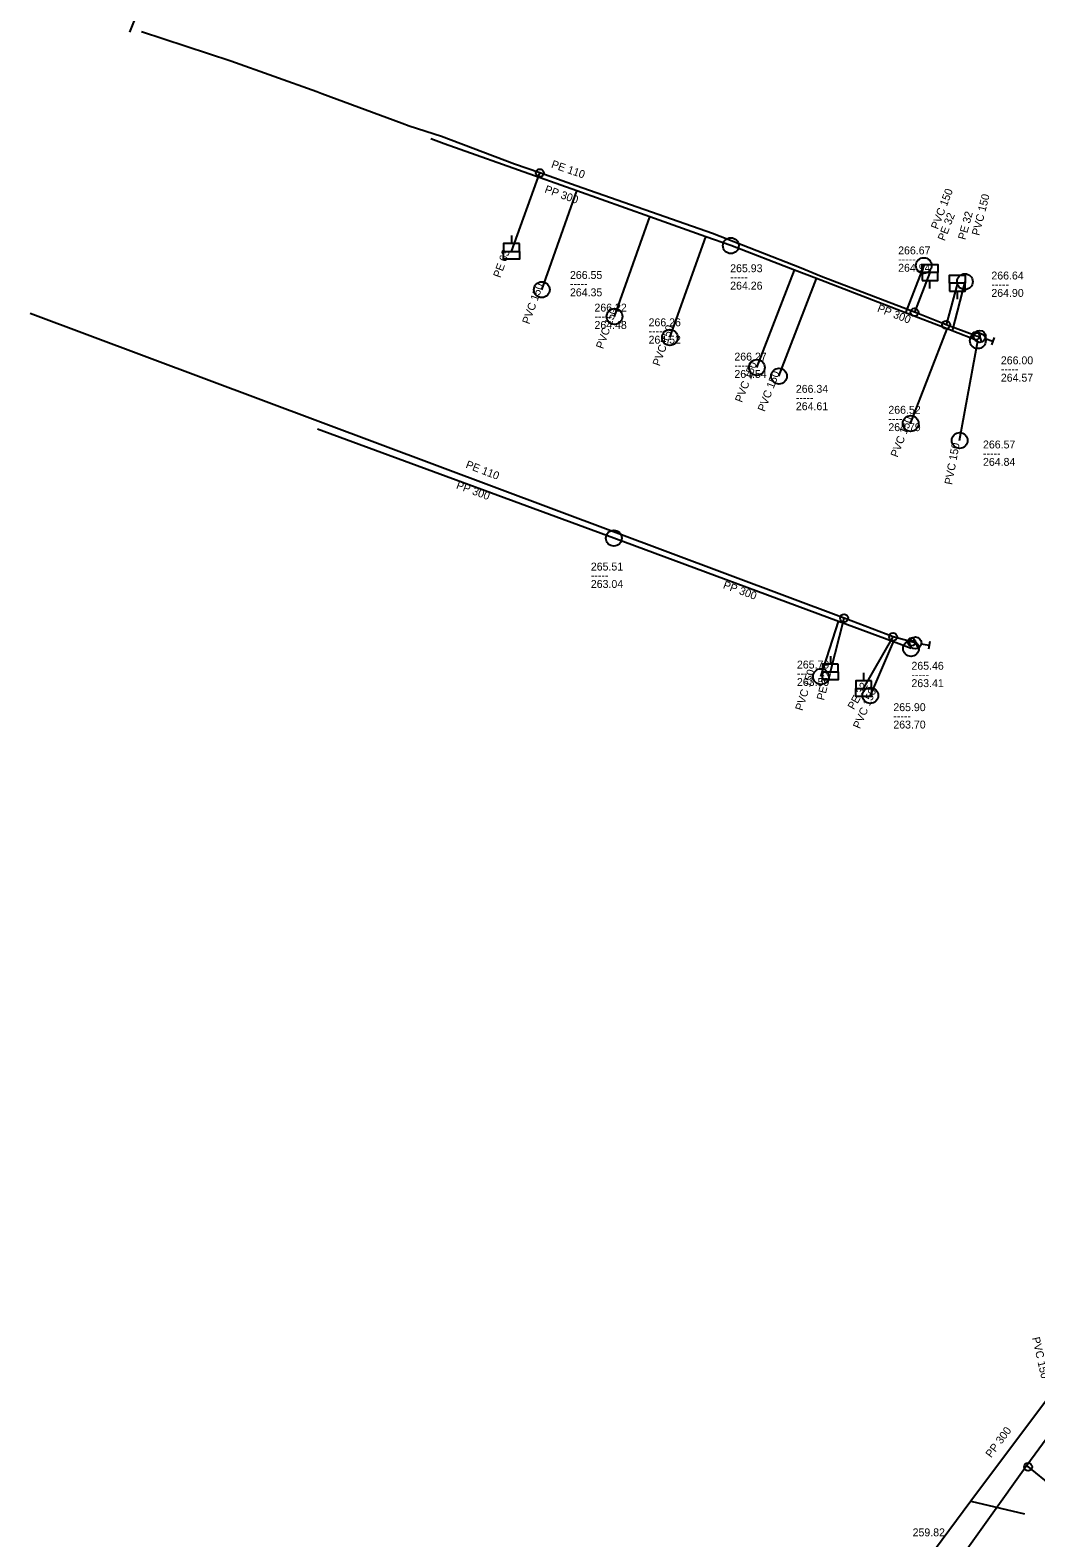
# Model space of a CAD drawing. Extents: x -770828 to -770111, y -1050344 to -1049447.
# Drawn here: x -770717.1 to -770589.8, y -1049916.1 to -1049725.3 of the extents above; entities that cross this region are included whole.
import ezdxf

# ---------------------------------------------------------------- set-up
doc = ezdxf.new("R2010")
doc.units = 0
doc.layers.add('Level 0', color=7, linetype='Continuous')

msp = doc.modelspace()

# ---------------------------------------------------------------- linework, layer by layer
at = {"layer": 'Level 0'}
for p, q in [((-770692.65, -1049695.96), (-770704.51, -1049725.54)), ((-770691.67, -1049729.23), (-770703, -1049725.52)), ((-770680.8, -1049733.09), (-770691.67, -1049729.23)), ((-770680.15, -1049733.34), (-770680.8, -1049733.09)), ((-770669.97, -1049737.13), (-770680.15, -1049733.34)), ((-770669.12, -1049737.44), (-770669.97, -1049737.13)), ((-770665.02, -1049738.76), (-770669.12, -1049737.44)), ((-770664.68, -1049739.67), (-770666.37, -1049739.07)), ((-770655.79, -1049742.26), (-770665.02, -1049738.76)), ((-770662.67, -1049740.39), (-770664.68, -1049739.67)), ((-770647.88, -1049745.64), (-770662.67, -1049740.39)), ((-770652.57, -1049743.37), (-770655.79, -1049742.26)), ((-770656.16, -1049753.29), (-770652.57, -1049743.37)), ((-770647.95, -1049744.98), (-770652.57, -1049743.37)), ((-770630.69, -1049751.04), (-770647.95, -1049744.98)), ((-770652.32, -1049758.14), (-770647.88, -1049745.64)), ((-770638.64, -1049748.93), (-770647.88, -1049745.64)), ((-770643.12, -1049761.54), (-770638.64, -1049748.93)), ((-770631.57, -1049751.44), (-770638.64, -1049748.93)), ((-770656.16, -1049751.29), (-770656.16, -1049752.29)), ((-770636.1, -1049764.19), (-770631.57, -1049751.44)), ((-770628.39, -1049752.57), (-770631.57, -1049751.44)), ((-770619.5, -1049755.42), (-770630.69, -1049751.04)), ((-770620.35, -1049755.67), (-770628.39, -1049752.57)), ((-770625.09, -1049767.99), (-770620.35, -1049755.67)), ((-770617.55, -1049756.74), (-770620.35, -1049755.67)), ((-770616.95, -1049756.48), (-770619.5, -1049755.42)), ((-770603.97, -1049755.09), (-770606.28, -1049761.08)), ((-770603.19, -1049755.97), (-770605.14, -1049761)), ((-770622.3, -1049769.08), (-770617.55, -1049756.74)), ((-770606.28, -1049761.08), (-770617.55, -1049756.74)), ((-770605.14, -1049761), (-770616.95, -1049756.48)), ((-770603.19, -1049757.97), (-770603.19, -1049756.97)), ((-770599.71, -1049757.32), (-770601.14, -1049762.58)), ((-770598.76, -1049757.13), (-770600.36, -1049763.36)), ((-770599.71, -1049759.32), (-770599.71, -1049758.32)), ((-770614.05, -1049799.7), (-770717.08, -1049761.16)), ((-770601.02, -1049763.1), (-770606.28, -1049761.08)), ((-770601.14, -1049762.58), (-770605.14, -1049761)), ((-770605.63, -1049775.08), (-770601.02, -1049763.1)), ((-770605.63, -1049775.08), (-770601.02, -1049763.1)), ((-770597.38, -1049763.97), (-770601.14, -1049762.58)), ((-770600.36, -1049763.36), (-770601.02, -1049763.1)), ((-770597.13, -1049764.6), (-770600.36, -1049763.36)), ((-770597.38, -1049763.97), (-770596.88, -1049764.06)), ((-770597.11, -1049763.35), (-770596.65, -1049764.77)), ((-770599.43, -1049777.22), (-770597.13, -1049764.6)), ((-770596.18, -1049764.32), (-770595.24, -1049764.66)), ((-770595.06, -1049764.19), (-770595.41, -1049765.13)), ((-770643.2, -1049789.59), (-770680.7, -1049775.77)), ((-770614.77, -1049800.13), (-770643.2, -1049789.59)), ((-770616.98, -1049807.1), (-770614.77, -1049800.13)), ((-770615.79, -1049806.51), (-770614.05, -1049799.7)), ((-770607.8, -1049802.7), (-770614.77, -1049800.13)), ((-770607.85, -1049802.08), (-770614.05, -1049799.7)), ((-770611.58, -1049808.62), (-770607.85, -1049802.08)), ((-770605.52, -1049802.71), (-770607.85, -1049802.08)), ((-770605.37, -1049802.18), (-770604.67, -1049803.5)), ((-770610.73, -1049809.5), (-770607.8, -1049802.7)), ((-770605.58, -1049803.54), (-770607.8, -1049802.7)), ((-770605.02, -1049802.84), (-770605.52, -1049802.71)), ((-770604.28, -1049802.97), (-770603.3, -1049803.14)), ((-770603.21, -1049802.65), (-770603.38, -1049803.64)), ((-770615.79, -1049804.51), (-770615.79, -1049805.51)), ((-770611.58, -1049806.62), (-770611.58, -1049807.62)), ((-770590.92, -1049906.89), (-770570.29, -1049878.63)), ((-770588.42, -1049898.65), (-770598, -1049911.45)), ((-770606.25, -1049928.29), (-770590.92, -1049906.89)), ((-770590.92, -1049906.89), (-770590.76, -1049907.11)), ((-770590.76, -1049907.11), (-770587.77, -1049909.53)), ((-770598, -1049911.45), (-770602.63, -1049917.64)), ((-770598, -1049911.45), (-770591.23, -1049913.04))]:
    msp.add_line(p, q, dxfattribs=at)
for points in [[(-770655.16, -1049752.29), (-770657.16, -1049752.29), (-770657.16, -1049753.29), (-770655.16, -1049753.29)], [(-770604.19, -1049756.97), (-770602.19, -1049756.97), (-770602.19, -1049755.97), (-770604.19, -1049755.97)], [(-770600.71, -1049758.32), (-770598.71, -1049758.32), (-770598.71, -1049757.32), (-770600.71, -1049757.32)], [(-770614.79, -1049805.51), (-770616.79, -1049805.51), (-770616.79, -1049806.51), (-770614.79, -1049806.51)], [(-770610.58, -1049807.62), (-770612.58, -1049807.62), (-770612.58, -1049808.62), (-770610.58, -1049808.62)]]:
    msp.add_lwpolyline(points, close=True, dxfattribs=at)
for points in [[(-770655.16, -1049753.29), (-770655.16, -1049754.29), (-770657.16, -1049754.29), (-770657.16, -1049753.29)], [(-770604.19, -1049755.97), (-770604.19, -1049754.97), (-770602.19, -1049754.97), (-770602.19, -1049755.97)], [(-770600.71, -1049757.32), (-770600.71, -1049756.32), (-770598.71, -1049756.32), (-770598.71, -1049757.32)], [(-770614.79, -1049806.51), (-770614.79, -1049807.51), (-770616.79, -1049807.51), (-770616.79, -1049806.51)], [(-770610.58, -1049808.62), (-770610.58, -1049809.62), (-770612.58, -1049809.62), (-770612.58, -1049808.62)]]:
    msp.add_lwpolyline(points, dxfattribs=at)
for centre, radius in [((-770652.57, -1049743.37), 0.5), ((-770628.39, -1049752.57), 1), ((-770603.97, -1049755.09), 1), ((-770598.76, -1049757.13), 1), ((-770652.32, -1049758.14), 1), ((-770643.12, -1049761.54), 1), ((-770605.14, -1049761), 0.5), ((-770601.14, -1049762.58), 0.5), ((-770636.1, -1049764.19), 1), ((-770597.13, -1049764.6), 1), ((-770597.38, -1049763.97), 0.5), ((-770596.88, -1049764.06), 0.75), ((-770625.09, -1049767.99), 1), ((-770622.3, -1049769.08), 1), ((-770605.63, -1049775.08), 1), ((-770599.43, -1049777.22), 1), ((-770643.2, -1049789.59), 1), ((-770614.05, -1049799.7), 0.5), ((-770607.85, -1049802.08), 0.5), ((-770605.52, -1049802.71), 0.5), ((-770605.02, -1049802.84), 0.75), ((-770605.58, -1049803.54), 1), ((-770616.98, -1049807.1), 1), ((-770610.73, -1049809.5), 1), ((-770590.76, -1049907.11), 0.5)]:
    msp.add_circle(centre, radius, dxfattribs=at)

# ---------------------------------------------------------------- texts
for s, rotation, p in [('PE 110', 340.98, (-770651.2, -1049742.66)), ('PP 300', 340.457, (-770652.04, -1049745.83)), ('PVC 150', 68.911, (-770602.18, -1049750.58)), ('PVC 150', 75.596, (-770596.95, -1049751.36)), ('PE 32', 68.81, (-770601.32, -1049752.04)), ('PE 32', 74.791, (-770598.7, -1049751.9)), ('PE 63', 70.105, (-770657.57, -1049756.71)), ('PVC 150', 70.445, (-770653.9, -1049762.58)), ('PP 300', 338.939, (-770609.94, -1049760.88)), ('PVC 150', 70.441, (-770644.56, -1049765.71)), ('PVC 150', 70.44, (-770637.4, -1049767.88)), ('PVC 150', 68.956, (-770626.98, -1049772.49)), ('PVC 150', 68.947, (-770624.11, -1049773.65)), ('PVC 150', 68.953, (-770607.29, -1049779.43)), ('PVC 150', 79.671, (-770600.38, -1049782.88)), ('PE 110', 339, (-770662.03, -1049780.65)), ('PP 300', 339.769, (-770663.23, -1049783.27)), ('PP 300', 339.76, (-770629.45, -1049795.89)), ('PVC 150', 72.408, (-770619.33, -1049811.49)), ('PE 32', 75.667, (-770616.59, -1049810.17)), ('PE 32', 60.302, (-770612.81, -1049811.37)), ('PVC 150', 66.69, (-770612.06, -1049813.78)), ('PVC 150', 283.095, (-770590.28, -1049890.79)), ('PP 300', 53.187, (-770595.44, -1049906.02))]:
    msp.add_text(s, height=1, rotation=rotation, dxfattribs=at).set_placement(p)
for s, p in [('266.67', (-770607.21, -1049753.67)), ('-----', (-770607.21, -1049754.77)), ('266.55', (-770648.75, -1049756.78)), ('265.93', (-770628.47, -1049755.93)), ('264.94', (-770607.21, -1049755.87)), ('266.64', (-770595.41, -1049756.85)), ('-----', (-770648.75, -1049757.88)), ('264.35', (-770648.75, -1049758.98)), ('-----', (-770628.47, -1049757.03)), ('264.26', (-770628.47, -1049758.13)), ('-----', (-770595.41, -1049757.95)), ('264.90', (-770595.41, -1049759.05)), ('266.22', (-770645.65, -1049760.91)), ('-----', (-770645.65, -1049762.01)), ('264.48', (-770645.65, -1049763.11)), ('266.26', (-770638.8, -1049762.77)), ('-----', (-770638.8, -1049763.87)), ('264.52', (-770638.8, -1049764.97)), ('-----', (-770627.94, -1049768.21)), ('266.27', (-770627.94, -1049767.11)), ('266.00', (-770594.21, -1049767.58)), ('264.54', (-770627.94, -1049769.31)), ('-----', (-770594.21, -1049768.68)), ('264.57', (-770594.21, -1049769.78)), ('266.34', (-770620.16, -1049771.19)), ('-----', (-770620.16, -1049772.29)), ('264.61', (-770620.16, -1049773.39)), ('266.52', (-770608.45, -1049773.84)), ('-----', (-770608.45, -1049774.94)), ('264.79', (-770608.45, -1049776.04)), ('266.57', (-770596.47, -1049778.23)), ('-----', (-770596.47, -1049779.33)), ('264.84', (-770596.47, -1049780.43)), ('265.51', (-770646.11, -1049793.68)), ('-----', (-770646.11, -1049794.78)), ('263.04', (-770646.11, -1049795.88)), ('265.79', (-770620.02, -1049806.08)), ('265.46', (-770605.53, -1049806.23)), ('-----', (-770620.02, -1049807.18)), ('263.59', (-770620.02, -1049808.28)), ('-----', (-770605.53, -1049807.33)), ('263.41', (-770605.53, -1049808.43)), ('265.90', (-770607.82, -1049811.47)), ('-----', (-770607.82, -1049812.57)), ('263.70', (-770607.82, -1049813.67)), ('259.82', (-770605.38, -1049915.89))]:
    msp.add_text(s, height=1, dxfattribs=at).set_placement(p)

doc.saveas('drawing.dxf')
